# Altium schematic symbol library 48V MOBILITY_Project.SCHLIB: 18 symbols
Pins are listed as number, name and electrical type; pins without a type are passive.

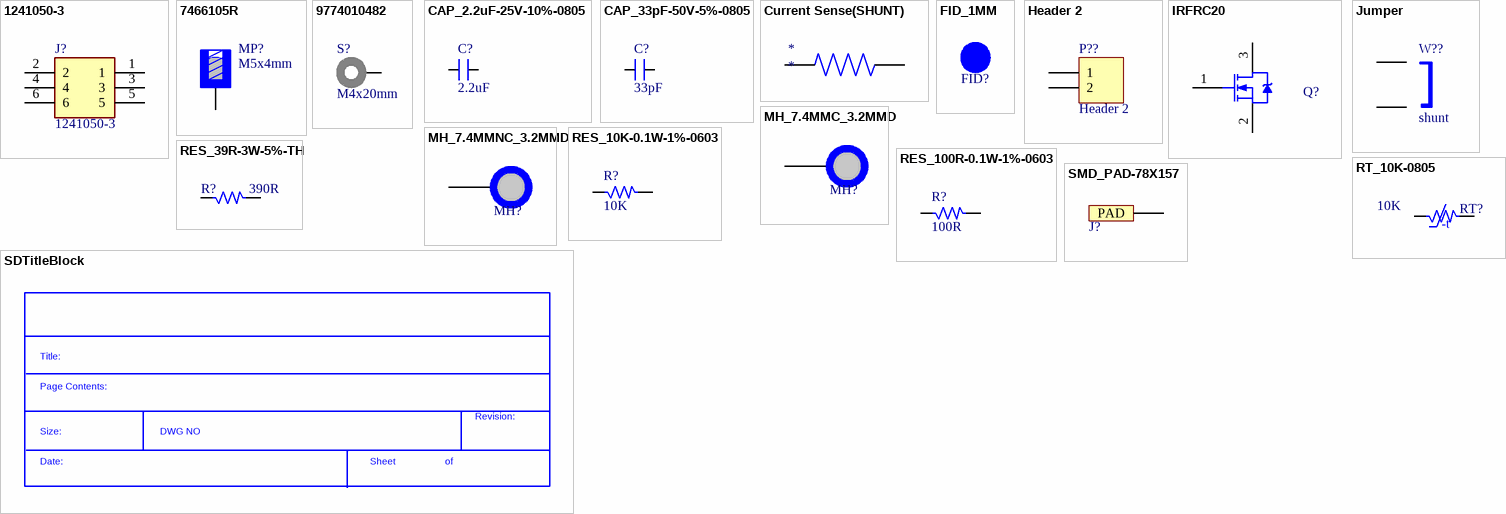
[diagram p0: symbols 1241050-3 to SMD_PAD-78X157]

## 1241050-3
designator J?
Connector; Manufacturer_Name: TE Connectivity
footprint 1241050-3
footprint 1241050-3
pins: 1 (power), 2, 3, 4, 5, 6

## 7466105R
designator MP?, comment M5x4mm
WP-SMBU SMT Internal blind-hole thread with pins, OD 9mm, M5x4mm, 70A; Manufacturer: Wurth Elektronik; Manufacturer Part Number: 7466105R; Thread: M5; Surface: Tin; Thread Length: 4mm
footprint 7466105R (SMD with internal blind-hole thread with Pin, M5 - 4 mm)
footprint 7466005R
footprint Round Spacer
pins: 1

## 9774010482
designator S?, comment M4x20mm
WA-SMSI SMT Steel Spacer, internal Thread, OD 8.2mm, M4x1mm; Manufacturer Part Number: 9774010482; Manufacturer: Wurth Elektronik; Inner Diameter: 5.2mm; Surface: Tin; Thread: M4
footprint 9774010482
footprint 15mm spacer
footprint 15mm spacer
footprint 15mm spacer
footprint 15mm spacer
footprint 15mm spacer
pins: 1

## CAP_2.2uF-25V-10%-0805
designator C?, comment 2.2uF
2.2µF ±10% 25V Ceramic Capacitor X7R 0805 (2012 Metric); Manufacturer: KEMET; Manufacturer Part Number: CL21B225KAFNFNE; Alternate Part Number-1: NA
footprint CAP_0805 (Ceramic Capacitor)
footprint CAP_1210 (Ceramic Capacitor)
footprint MY_1812
footprint CAP_1812
pins: 1, 2

## CAP_33pF-50V-5%-0805
designator C?, comment 33pF
33pF ±5% 50V Ceramic Capacitor C0G, NP0 0805 (2012 Metric); Manufacturer: Samsung; Manufacturer Part Number: CL21C330JBANNNC; Alternate Part Number-1: NA
footprint CAP_0805 (Ceramic Capacitor)
footprint MY_0805
pins: 1, 2

## Current Sense(SHUNT)
designator *
pins: 1, 2

## FID_1MM
designator FID?  (value not drawn)  (no BOM)
Fiducial 40 mil Diameter and 120 mil Mask
footprint FID_40x20D

## Header 2
designator P??
Header, 2-Pin
footprint HDR1X2 (Connector; Header; 2 Position)
signal-integrity model Connector
pins: 1, 2

## IRFRC20
designator Q?, comment HYG085N04LA1D  (value not drawn)
HEXFET Power MOSFET; Note: Pin 2 is trimmed and is electrically connected to Drain.
footprint TO-252AA_N (D-PAK, 4-Leads, Body 6.1x6.5mm, Pitch 2.28mm, Lead Span 9.9mm, IPC Medium Density)
footprint TO-252AA_L (D-PAK, 4-Leads, Body 6.1x6.5mm, Pitch 2.28mm, Lead Span 9.9mm, IPC High Density)
footprint TO-252AA_M (D-PAK, 4-Leads, Body 6.1x6.5mm, Pitch 2.28mm, Lead Span 9.9mm, IPC Low Density)
footprint IRFRC20
footprint MY_TO252
footprint TO-252-2L
footprint D2PAK
pins: 1 G, 2 S, 3 D

## Jumper
designator W??, comment shunt
Jumper Wire; ASiD Part Number: Jumper-AS
footprint My_1X02
footprint MY_JUMPER_5mm
footprint MY_JUMPER_7mm
footprint MY_JUMPER_10mm
footprint MY_JUMPER_12mm
footprint MY_JUMPER_15mm
footprint MY_JUMPER_20mm
footprint MY_JUMPER_25mm
footprint MY_JUMPER_30mm
footprint MY_0805
pins: 1, 2

## MH_7.4MMC_3.2MMD
designator MH?  (value not drawn)  (no BOM)
Mounting Hole 7.4 mm diameter 3.2 mm Drill
footprint MH_7.4MMD_3.2MMD
footprint MOUNTING (MH)
footprint MOUNTING (MH)
footprint PCBComponent_1
pins: 1

## MH_7.4MMNC_3.2MMD
designator MH?  (value not drawn)  (no BOM)
Hole 7.4mm Diameter (Non copper ),3.2mm drill NPTH
footprint MH_7.4MMNC_3.2MMD
footprint MOUNTING (MH)
footprint PCBComponent_1
pins: 1

## RES_10K-0.1W-1%-0603
designator R?, comment 10K
10 kOhms ±1% 0.1W, 1/10W Chip Resistor 0603 (1608 Metric) Automotive AEC-Q200 Thick Film; Manufacturer: Walsin; Manufacturer Part Number: WR06X1002FTL; Alternate Part Number-1: 0603WAJ0103T5E
footprint RES_0603
footprint MY_1206
footprint MY_0805
pins: 1, 2

## RES_39R-3W-5%-TH
designator R?, comment 390R
39 Ohms ±5% 3W Through Hole Resistor Axial Flame Proof, Safety Wirewound; Manufacturer: Stackpole Electronics; Manufacturer Part Number: RWM041039R0JR15E1; Alternate Part Number-1: NA
footprint RES_669_551X197_TH
footprint MY_0805
footprint MY_0603
footprint MY_0402
pins: 1, 2

## RES_100R-0.1W-1%-0603
designator R?, comment 100R
100 Ohms ±1% 0.1W, 1/10W Chip Resistor 0603 (1608 Metric) Thick Film; Manufacturer: Walsin; Manufacturer Part Number: WR06X1000FTL; Alternate Part Number-1: MR06X1000FTL
footprint RES_0603
footprint MY_1206
footprint MY_1206
pins: 1, 2

## RT_10K-0805
designator RT?, comment 10K
NTC Thermistor 10k 0805 (2012 Metric); Manufacturer: Vishay BCcomponents; Manufacturer Part Number: NCP21XV103J03RA; Alternate Part Number-1: NA
footprint RES_0805
pins: 1, 2

## SDTitleBlock
designator *??  (value not drawn)  (graphical)

## SMD_PAD-78X157
designator J?, comment 78X157 PAD  (value not drawn)
SMD Pad of 2mm x 4mm 1 pin; Manufacturer: NA
footprint SMD-PAD_78X157 (SMD PAD)
footprint VDDS PAD
pins: 1 PAD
